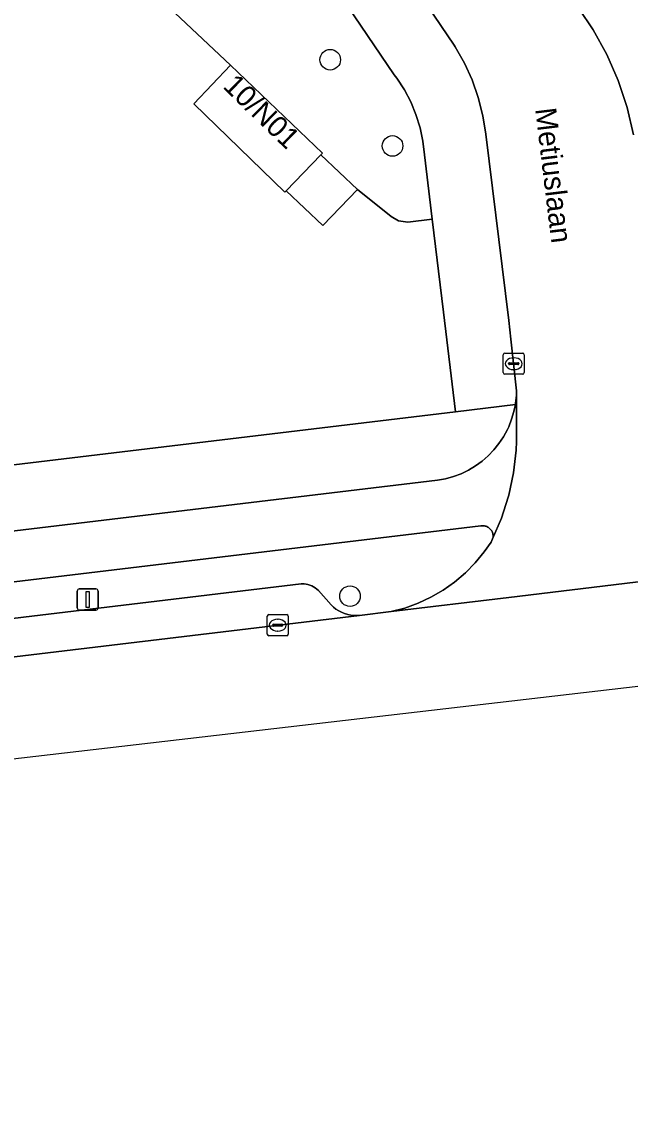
# Model space of a CAD drawing. Extents: x 159888 to 160761, y 384031 to 384750.
# Drawn here: x 160476.9 to 160505.8, y 384134.1 to 384185.7 of the extents above; entities that cross this region are included whole.
import ezdxf

# ---------------------------------------------------------------- set-up
doc = ezdxf.new("R2010")
doc.units = 0
for name, color, linetype in [('IMGEO_Berm_open', 7, 'Continuous'), ('IMGEO_Boom', 7, 'Continuous'), ('IMGEO_Fietspad_open', 7, 'Continuous'), ('IMGEO_Groenvoorziening', 7, 'Continuous'), ('IMGEO_Kolk', 7, 'Continuous'), ('IMGEO_Lichtmast', 7, 'Continuous'), ('IMGEO_Openbare_ruimte_label', 7, 'Continuous'), ('IMGEO_Pand', 7, 'Continuous'), ('IMGEO_Pand_nummerreeks', 7, 'Continuous'), ('IMGEO_Parkeervlak_open', 7, 'Continuous'), ('IMGEO_Rijbaan_lokaal_gesloten', 7, 'Continuous'), ('IMGEO_Rijbaan_lokaal_open', 7, 'Continuous'), ('IMGEO_Voetpad_open', 7, 'Continuous')]:
    doc.layers.add(name, color=color, linetype=linetype)

msp = doc.modelspace()

# ---------------------------------------------------------------- linework, layer by layer
at = {"layer": 'IMGEO_Berm_open'}
msp.add_lwpolyline([(160427.443, 384151.436), (160490.133, 384158.969), (160490.176, 384158.97), (160490.273, 384158.967), (160490.368, 384158.955), (160490.462, 384158.934), (160490.554, 384158.906), (160490.643, 384158.869), (160490.728, 384158.824), (160490.809, 384158.772), (160490.885, 384158.713), (160490.955, 384158.647), (160491.556, 384157.963), (160491.67, 384157.859), (160491.793, 384157.765), (160491.924, 384157.683), (160492.061, 384157.613), (160492.205, 384157.556), (160492.352, 384157.511), (160492.504, 384157.48), (160492.657, 384157.463), (160492.811, 384157.459), (160492.911, 384157.464), (160494.41, 384157.644), (160495.06, 384157.815), (160495.692, 384158.043), (160496.301, 384158.326), (160496.882, 384158.663), (160497.431, 384159.05), (160497.943, 384159.485), (160498.414, 384159.964), (160498.84, 384160.483), (160499.162, 384160.948), (160499.239, 384161.104), (160499.249, 384161.146), (160499.255, 384161.19), (160499.258, 384161.233), (160499.256, 384161.277), (160499.251, 384161.32), (160499.242, 384161.363), (160499.229, 384161.404), (160499.212, 384161.445), (160499.192, 384161.483), (160499.169, 384161.52), (160499.142, 384161.554), (160499.112, 384161.586), (160499.08, 384161.615), (160499.045, 384161.642), (160499.008, 384161.664), (160498.969, 384161.684), (160498.928, 384161.7), (160498.886, 384161.712), (160498.844, 384161.721), (160498.8, 384161.725), (160498.757, 384161.726), (160498.713, 384161.723), (160498.671, 384161.716), (160427.759, 384153.215)], dxfattribs=at)
at = {"layer": 'IMGEO_Boom'}
for centre in [(160491.518, 384183.871), (160494.482, 384179.773), (160492.459, 384158.379)]:
    msp.add_circle(centre, 0.489, dxfattribs=at)
at = {"layer": 'IMGEO_Fietspad_open'}
for points in [[(160498.671, 384161.716), (160498.713, 384161.723), (160498.757, 384161.726), (160498.8, 384161.725), (160498.844, 384161.721), (160498.886, 384161.712), (160498.928, 384161.7), (160498.969, 384161.684), (160499.008, 384161.664), (160499.045, 384161.642), (160499.08, 384161.615), (160499.112, 384161.586), (160499.142, 384161.554), (160499.169, 384161.52), (160499.192, 384161.483), (160499.212, 384161.445), (160499.229, 384161.404), (160499.242, 384161.363), (160499.251, 384161.32), (160499.256, 384161.277), (160499.258, 384161.233), (160499.255, 384161.19), (160499.249, 384161.146), (160499.239, 384161.104), (160499.652, 384162.08), (160499.976, 384163.088), (160500, 384163.177), (160500.226, 384164.24), (160500.355, 384165.318), (160500.379, 384165.727), (160500.377, 384168.143), (160500.369, 384167.924), (160500.327, 384167.538), (160500.317, 384167.486), (160500.252, 384167.157), (160500.142, 384166.785), (160500, 384166.424), (160499.938, 384166.291), (160499.753, 384165.95), (160499.538, 384165.627), (160499.295, 384165.325), (160499.026, 384165.046), (160498.734, 384164.792), (160498.419, 384164.565), (160498.086, 384164.366), (160497.737, 384164.199), (160497.373, 384164.063), (160497, 384163.961), (160496.618, 384163.892), (160427.484, 384155.614)], [(160399.716, 384142.915), (160400.343, 384143.286), (160400.825, 384143.559), (160401.674, 384144.039), (160404.278, 384145.513), (160407.348, 384147.131), (160411.719, 384149.018), (160416.241, 384150.508), (160421.097, 384151.881), (160427.759, 384153.215), (160498.671, 384161.716)]]:
    msp.add_lwpolyline(points, dxfattribs=at)
at = {"layer": 'IMGEO_Groenvoorziening'}
msp.add_lwpolyline([(160480.257, 384204.274), (160469.497, 384195.444), (160472.691, 384191.58), (160475.677, 384194.048), (160486.78, 384183.613), (160491.144, 384179.427), (160491.067, 384179.347), (160492.813, 384177.71), (160494.41, 384176.424), (160494.765, 384176.208), (160495.213, 384176.159), (160496.371, 384176.297), (160496.006, 384179.357), (160495.925, 384180.003), (160495.787, 384180.64), (160495.592, 384181.262), (160495.343, 384181.864), (160495.041, 384182.441), (160494.689, 384182.989), (160494.565, 384183.158)], close=True, dxfattribs=at)
for points in [[(160496.371, 384176.297), (160495.213, 384176.159), (160494.765, 384176.208), (160494.41, 384176.424), (160492.813, 384177.71), (160491.169, 384175.986), (160489.431, 384177.643), (160489.36, 384177.569), (160485.029, 384181.774), (160486.78, 384183.613), (160475.677, 384194.048), (160472.691, 384191.58), (160442.427, 384166.564)], [(160443.941, 384164.258), (160440.992, 384161.842), (160440.695, 384160.33), (160497.469, 384167.144), (160496.899, 384171.869), (160496.371, 384176.297)]]:
    msp.add_lwpolyline(points, dxfattribs=at)
at = {"layer": 'IMGEO_Kolk'}
for p, q in [((160499.74, 384169), (160499.74, 384169.852)), ((160499.815, 384169.926), (160500.667, 384169.926)), ((160500.741, 384169.852), (160500.741, 384169)), ((160499.999, 384169.42), (160499.999, 384169.432)), ((160500.437, 384169.383), (160500.039, 384169.383)), ((160500.042, 384169.469), (160500.44, 384169.469)), ((160500.228, 384169.706), (160500.253, 384169.706)), ((160500.483, 384169.432), (160500.483, 384169.42)), ((160500.667, 384168.926), (160499.815, 384168.926)), ((160500.251, 384169.146), (160500.226, 384169.146)), ((160488.599, 384157.5), (160489.451, 384157.5)), ((160488.524, 384156.574), (160488.524, 384157.426)), ((160488.783, 384156.994), (160488.783, 384157.006)), ((160489.221, 384156.957), (160488.823, 384156.957)), ((160488.826, 384157.043), (160489.224, 384157.043)), ((160489.012, 384157.28), (160489.037, 384157.28)), ((160489.267, 384157.006), (160489.267, 384156.994)), ((160489.525, 384157.426), (160489.525, 384156.574)), ((160489.451, 384156.5), (160488.599, 384156.5)), ((160489.035, 384156.72), (160489.01, 384156.72))]:
    msp.add_line(p, q, dxfattribs=at)
for points in [[(160499.74, 384169), (160499.74, 384169.852)], [(160499.815, 384169.926), (160500.667, 384169.926)], [(160500.741, 384169.852), (160500.741, 384169)], [(160500.667, 384168.926), (160499.815, 384168.926)], [(160488.599, 384157.5), (160489.451, 384157.5)], [(160488.524, 384156.574), (160488.524, 384157.426)], [(160489.525, 384157.426), (160489.525, 384156.574)], [(160489.451, 384156.5), (160488.599, 384156.5)]]:
    msp.add_lwpolyline(points, dxfattribs=at)
for centre, radius, start, end in [((160499.817, 384169.85), 0.0765, 91.552, 178.448), ((160499.817, 384169.85), 0.0765, 91.552, 178.448), ((160500.665, 384169.85), 0.0765, 1.552, 88.448), ((160500.665, 384169.85), 0.0765, 1.552, 88.448), ((160500.039, 384169.429), 0.0403, 85.8775, 175.7526), ((160500.036, 384169.419), 0.0366, 178.938, 274.7102), ((160500.44, 384169.426), 0.043, 264.8664, 352.4533), ((160500.444, 384169.431), 0.0386, 1.7309, 96.639), ((160499.817, 384169.002), 0.0765, 181.552, 268.448), ((160499.817, 384169.002), 0.0765, 181.552, 268.448), ((160500.665, 384169.002), 0.0765, 271.552, 358.448), ((160500.665, 384169.002), 0.0765, 271.552, 358.448), ((160488.601, 384157.424), 0.0765, 91.552, 178.448), ((160488.601, 384157.424), 0.0765, 91.552, 178.448), ((160489.449, 384157.424), 0.0765, 1.552, 88.448), ((160489.449, 384157.424), 0.0765, 1.552, 88.448), ((160488.823, 384157.003), 0.0403, 85.8775, 175.7526), ((160488.82, 384156.993), 0.0366, 178.938, 274.7102), ((160489.224, 384157), 0.043, 264.8664, 352.4533), ((160489.228, 384157.005), 0.0386, 1.7309, 96.639), ((160488.601, 384156.576), 0.0765, 181.552, 268.448), ((160488.601, 384156.576), 0.0765, 181.552, 268.448), ((160489.449, 384156.576), 0.0765, 271.552, 358.448), ((160489.449, 384156.576), 0.0765, 271.552, 358.448)]:
    msp.add_arc(centre, radius, start, end, dxfattribs=at)
for centre, major_axis, ratio, start_param, end_param in [((160500.227, 384169.426), (-0.387, 0.002), 0.722429, 4.712389, 7.853982), ((160500.252, 384169.426), (-0.39, 0.002), 0.717154, 1.570796, 4.712389), ((160489.011, 384157), (-0.387, 0.002), 0.722429, 4.712389, 7.853982), ((160489.036, 384157), (-0.39, 0.002), 0.717154, 1.570796, 4.712389)]:
    msp.add_ellipse(centre, major_axis=major_axis, ratio=ratio, start_param=start_param, end_param=end_param, dxfattribs=at)
at = {"layer": 'IMGEO_Lichtmast'}
for p, q in [((160479.493, 384157.82), (160479.493, 384158.62)), ((160479.493, 384158.62), (160479.493, 384157.82)), ((160479.593, 384158.72), (160480.383, 384158.72)), ((160480.383, 384158.72), (160479.593, 384158.72)), ((160480.483, 384158.62), (160480.483, 384157.82)), ((160480.483, 384157.82), (160480.483, 384158.62)), ((160480.383, 384157.72), (160479.593, 384157.72)), ((160479.593, 384157.72), (160480.383, 384157.72))]:
    msp.add_line(p, q, dxfattribs=at)
msp.add_lwpolyline([(160479.913, 384158.595), (160480.063, 384158.595), (160480.063, 384157.845), (160479.913, 384157.845), (160479.913, 384158.595)], dxfattribs=at)
for centre, start, end in [((160479.593, 384158.62), 90, 180), ((160479.593, 384158.62), 90, 180), ((160480.383, 384158.62), 0, 90), ((160480.383, 384158.62), 360, 90), ((160479.593, 384157.82), 180, 270), ((160479.593, 384157.82), 180, 270), ((160480.383, 384157.82), 270, 0), ((160480.383, 384157.82), 270, 0)]:
    msp.add_arc(centre, 0.1, start, end, dxfattribs=at)
at = {"layer": 'IMGEO_Pand'}
msp.add_lwpolyline([(160486.78, 384183.613), (160485.029, 384181.774), (160489.36, 384177.569), (160489.431, 384177.643), (160491.067, 384179.347), (160491.144, 384179.427)], close=True, dxfattribs=at)
at = {"layer": 'IMGEO_Parkeervlak_open'}
msp.add_lwpolyline([(160427.962, 384149.681), (160492.911, 384157.464), (160492.811, 384157.459), (160492.657, 384157.463), (160492.504, 384157.48), (160492.352, 384157.511), (160492.205, 384157.556), (160492.061, 384157.613), (160491.924, 384157.683), (160491.793, 384157.765), (160491.67, 384157.859), (160491.556, 384157.963), (160490.955, 384158.647), (160490.885, 384158.713), (160490.809, 384158.772), (160490.728, 384158.824), (160490.643, 384158.869), (160490.554, 384158.906), (160490.462, 384158.934), (160490.368, 384158.955), (160490.273, 384158.967), (160490.176, 384158.97), (160490.133, 384158.969), (160427.443, 384151.436)], dxfattribs=at)
at = {"layer": 'IMGEO_Rijbaan_lokaal_gesloten'}
msp.add_lwpolyline([(160409.439, 384134.137), (160427.128, 384143.73), (160429.205, 384144.132), (160442.915, 384146.785), (160462.791, 384149.068), (160506.283, 384154.117), (160516.834, 384155.497), (160516.108, 384160.265), (160500, 384158.317), (160494.41, 384157.644), (160492.911, 384157.464), (160427.962, 384149.681), (160425.051, 384149.307), (160419.834, 384148.53), (160419.085, 384148.352)], dxfattribs=at)
at = {"layer": 'IMGEO_Rijbaan_lokaal_open'}
for points in [[(160505.94, 384180.299), (160505.629, 384181.607), (160505.201, 384182.882), (160504.662, 384184.113), (160504.014, 384185.292), (160503.336, 384186.31), (160502.084, 384188.18), (160500, 384191.296), (160499.06, 384192.709), (160497.556, 384194.968), (160493.2, 384201.491), (160489.717, 384206.618), (160488.881, 384207.593)], [(160484.375, 384203.808), (160497.404, 384184.565), (160497.456, 384184.484), (160497.894, 384183.713), (160498.263, 384182.907), (160498.557, 384182.071), (160498.776, 384181.212), (160498.917, 384180.337), (160500, 384171.476), (160500.107, 384170.589), (160500.377, 384168.143), (160500.379, 384165.727), (160500.355, 384165.318), (160500.226, 384164.24), (160500, 384163.177), (160499.976, 384163.088), (160499.652, 384162.08), (160499.239, 384161.104), (160499.162, 384160.948), (160498.84, 384160.483), (160498.414, 384159.964), (160497.943, 384159.485), (160497.431, 384159.05), (160496.882, 384158.663), (160496.301, 384158.326), (160495.692, 384158.043), (160495.06, 384157.815), (160494.41, 384157.644), (160500, 384158.317), (160516.108, 384160.265)]]:
    msp.add_lwpolyline(points, dxfattribs=at)
at = {"layer": 'IMGEO_Voetpad_open'}
for points in [[(160488.881, 384207.593), (160489.717, 384206.618), (160493.2, 384201.491), (160497.556, 384194.968), (160499.06, 384192.709), (160499.476, 384192.985), (160500, 384192.201), (160502.5, 384188.456), (160502.084, 384188.18), (160503.336, 384186.31), (160504.014, 384185.292), (160504.662, 384184.113), (160505.201, 384182.882), (160505.629, 384181.607), (160505.94, 384180.299)], [(160480.257, 384204.274), (160494.565, 384183.158), (160494.689, 384182.989), (160495.041, 384182.441), (160495.343, 384181.864), (160495.592, 384181.262), (160495.787, 384180.64), (160495.925, 384180.003), (160496.006, 384179.357), (160496.371, 384176.297), (160496.899, 384171.869), (160497.469, 384167.144), (160500.317, 384167.486), (160500.327, 384167.538), (160500.369, 384167.924), (160500.377, 384168.143), (160500.107, 384170.589), (160500, 384171.476), (160498.917, 384180.337), (160498.776, 384181.212), (160498.557, 384182.071), (160498.263, 384182.907), (160497.894, 384183.713), (160497.456, 384184.484), (160497.404, 384184.565), (160484.375, 384203.808)], [(160496.618, 384163.892), (160497, 384163.961), (160497.373, 384164.063), (160497.737, 384164.199), (160498.086, 384164.366), (160498.419, 384164.565), (160498.734, 384164.792), (160499.026, 384165.046), (160499.295, 384165.325), (160499.538, 384165.627), (160499.753, 384165.95), (160499.938, 384166.291), (160500, 384166.424), (160500.142, 384166.785), (160500.252, 384167.157), (160500.317, 384167.486), (160497.469, 384167.144), (160440.695, 384160.33), (160425.801, 384158.542), (160419.388, 384157.193)], [(160397.757, 384144.577), (160402.131, 384147.008), (160404.263, 384148.273), (160408.933, 384150.481), (160414.196, 384152.415), (160420.542, 384154.247), (160427.484, 384155.614), (160496.618, 384163.892)]]:
    msp.add_lwpolyline(points, dxfattribs=at)
msp.add_lwpolyline([(160491.067, 384179.347), (160489.431, 384177.643), (160491.169, 384175.986), (160492.813, 384177.71)], close=True, dxfattribs=at)

# ---------------------------------------------------------------- texts
at = {"layer": 'IMGEO_Openbare_ruimte_label'}
msp.add_text('Metiuslaan', height=1, rotation=276.9474, dxfattribs=at).set_placement((160501.256, 384181.532))
at = {"layer": 'IMGEO_Pand_nummerreeks'}
msp.add_text('10/N01', height=1, rotation=315.8479, dxfattribs=at).set_placement((160486.368, 384182.564))

doc.saveas('drawing.dxf')
